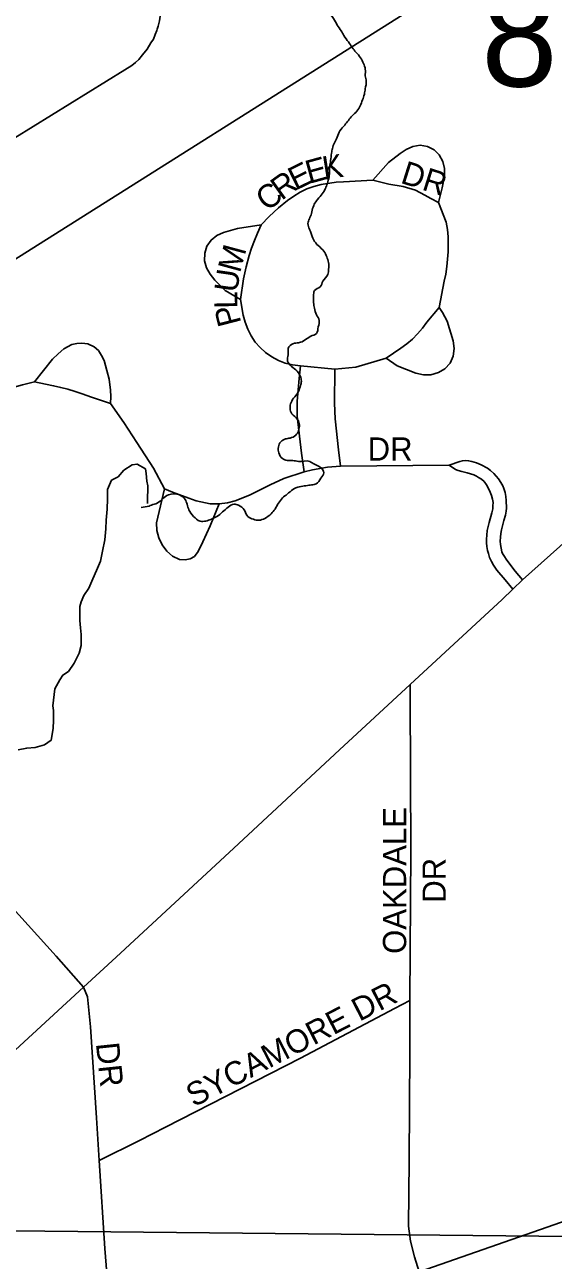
# Model space of a CAD drawing. Extents: x 1587405 to 1714697, y 1028970 to 1155083.
# Drawn here: x 1657853 to 1658990, y 1113359 to 1116017 of the extents above; entities that cross this region are included whole.
import ezdxf

# ---------------------------------------------------------------- set-up
doc = ezdxf.new("R2010")
doc.units = 0
for name, color, linetype in [('GM_X_City_Street', 7, 'Continuous'), ('GM_X_City_Street_Text', 7, 'Continuous'), ('GM_X_Minor_River', 7, 'Continuous'), ('GM_X_Rail_Line', 7, 'Continuous'), ('GM_X_Section', 7, 'Continuous'), ('GM_X_Section_Text', 7, 'Continuous'), ('GM_X_State_Route', 7, 'Continuous'), ('GM_X_US_Route', 7, 'Continuous')]:
    doc.layers.add(name, color=color, linetype=linetype)

msp = doc.modelspace()

# ---------------------------------------------------------------- linework, layer by layer
at = {"layer": 'GM_X_City_Street'}
for points in [[(1657832.1, 1115773.7), (1658068.7, 1115919.8), (1658083.3, 1115929.3), (1658091.2, 1115935.4), (1658098.7, 1115942.3), (1658106.7, 1115951.9), (1658116.3, 1115964.6), (1658124.7, 1115977.9), (1658129.8, 1115986.1), (1658134, 1115995.8), (1658137.4, 1116004.3), (1658138.2, 1116007.2), (1658140, 1116013.6), (1658142.8, 1116025.2), (1658145.6, 1116044.7)], [(1658743.2, 1115634.5), (1658751.3, 1115665.9), (1658756.1, 1115691.5), (1658755.8, 1115707.4), (1658752.2, 1115722.7), (1658744.7, 1115736.6), (1658733.6, 1115747.9), (1658719.5, 1115754.9), (1658703.9, 1115757.4), (1658688.3, 1115754.9), (1658673.8, 1115748.7), (1658660.7, 1115739.9), (1658635.6, 1115720.5), (1658601.9, 1115682.1)], [(1658601.9, 1115682.1), (1658539.2, 1115679.2), (1658522.9, 1115678.1), (1658490.7, 1115673.1), (1658475.2, 1115669.1), (1658460, 1115663.5), (1658445.5, 1115656.6), (1658431.7, 1115648.2), (1658418.7, 1115638.6), (1658399.2, 1115623.1), (1658378.9, 1115604.4), (1658361.8, 1115586.5)], [(1658743.2, 1115634.5), (1658726.9, 1115643.2), (1658713.8, 1115650), (1658693.4, 1115661), (1658666.9, 1115668.6), (1658636.5, 1115673.9), (1658601.9, 1115682.1)], [(1658744.9, 1115408.3), (1658755.4, 1115465), (1658758.9, 1115480.6), (1658761.4, 1115496.4), (1658763.8, 1115528.6), (1658763.8, 1115560.7), (1658762.3, 1115576.6), (1658759.5, 1115592.2), (1658743.2, 1115634.5)], [(1658361.8, 1115586.5), (1658310.7, 1115578.4), (1658280.7, 1115570.1), (1658266.3, 1115563.4), (1658254, 1115553.4), (1658245.1, 1115540.4), (1658240.4, 1115525.1), (1658240.1, 1115509.2), (1658244.2, 1115493.8), (1658251.9, 1115480), (1658262, 1115467.6), (1658284.6, 1115445.1), (1658317.4, 1115426)], [(1658361.8, 1115586.5), (1658353.7, 1115568.7), (1658347.1, 1115552.8), (1658341.2, 1115536.1), (1658336.2, 1115520.7), (1658329.4, 1115496.3), (1658323.6, 1115470.3), (1658317.4, 1115426)], [(1658317.4, 1115426), (1658323, 1115392.4), (1658327.2, 1115376.8), (1658332.9, 1115361.9), (1658340.3, 1115347.6), (1658349.1, 1115334.3), (1658359.5, 1115322.2), (1658371.4, 1115311.5), (1658384.5, 1115302.4), (1658398.8, 1115294.8), (1658413.3, 1115288.7), (1658428.8, 1115284.9), (1658446.5, 1115282.7)], [(1658630.8, 1115299.4), (1658662, 1115320.9), (1658674.9, 1115330.3), (1658687, 1115340.7), (1658698.3, 1115352), (1658708.7, 1115364.1), (1658718.2, 1115376.9), (1658744.9, 1115408.3)], [(1658630.8, 1115299.4), (1658654.1, 1115283.2), (1658694.5, 1115267.3), (1658710.6, 1115263.7), (1658727, 1115263.9), (1658742.9, 1115268.4), (1658757, 1115276.9), (1658768, 1115289.1), (1658774.9, 1115304.1), (1658776.9, 1115320.4), (1658774.9, 1115336.7), (1658761.7, 1115379), (1658751.7, 1115397.8), (1658744.9, 1115408.3)], [(1657874.1, 1115248.8), (1657912.9, 1115297.5), (1657924.9, 1115308.8), (1657937.6, 1115319.5), (1657954.3, 1115328.8), (1657965.5, 1115331.3), (1657976.1, 1115332.1), (1657988.9, 1115330.4), (1658002.8, 1115323.7), (1658011.5, 1115316), (1658018.6, 1115305.6), (1658023.8, 1115294.2), (1658029.9, 1115272.7), (1658034.9, 1115254.2), (1658037.6, 1115230.4), (1658038.7, 1115216.9), (1658037.6, 1115202.3)], [(1658454, 1115054.7), (1658448.5, 1115094.9), (1658439.4, 1115175.1), (1658438.9, 1115207.4), (1658443.7, 1115255.6), (1658446.5, 1115282.7)], [(1658446.5, 1115282.7), (1658520, 1115275.9)], [(1658520, 1115275.9), (1658565.1, 1115280.3), (1658630.8, 1115299.4)], [(1658532.4, 1115067.1), (1658528.4, 1115102.1), (1658520.6, 1115168.9), (1658519.2, 1115202.5), (1658520, 1115275.9)], [(1657693, 1114961.3), (1657695.7, 1114981.9), (1657694.6, 1115014.3), (1657691.3, 1115048.4), (1657690.2, 1115070.6), (1657692.4, 1115103.1), (1657699.7, 1115131.2), (1657708.8, 1115150.7), (1657719.2, 1115165.7), (1657728.3, 1115178), (1657738.1, 1115187.8), (1657748.7, 1115196.5), (1657760.4, 1115206.3), (1657773.8, 1115214.7), (1657788.1, 1115221.7), (1657803, 1115227.1), (1657822.7, 1115234.7), (1657848.2, 1115242.3), (1657874.1, 1115248.8)], [(1657874.1, 1115248.8), (1657898, 1115243.3), (1657915.3, 1115240.1), (1657930.5, 1115236.1), (1657946.2, 1115232.6), (1657961.6, 1115228.2), (1657976.6, 1115222.6), (1657997, 1115215.8), (1658037.6, 1115202.3)], [(1658037.6, 1115202.3), (1658066.6, 1115161.2), (1658094.3, 1115118), (1658130.1, 1115062.7), (1658153.5, 1115018.3)], [(1658454, 1115054.7), (1658472.2, 1115059.5), (1658504.1, 1115064.9), (1658532.4, 1115067.1)], [(1658532.4, 1115067.1), (1658765.9, 1115069.1)], [(1658765.9, 1115069.1), (1658789.2, 1115077.5), (1658794.7, 1115078.9), (1658801.2, 1115079.5), (1658807.8, 1115078.9), (1658814.8, 1115077.3), (1658825, 1115074.3), (1658835.1, 1115070), (1658848.3, 1115062.8), (1658855, 1115057.8), (1658862.3, 1115051.1), (1658872.3, 1115039.8), (1658877.2, 1115032.3), (1658881.5, 1115025.1), (1658883.8, 1115019.2), (1658886.3, 1115010.8), (1658887.9, 1115002), (1658888.6, 1114993.2), (1658889.2, 1114976.9), (1658888.8, 1114970.3), (1658887.2, 1114961.7), (1658883.8, 1114950.4), (1658880.9, 1114939.1), (1658878.4, 1114930.1), (1658877.3, 1114922.4), (1658876.7, 1114914.5), (1658876.1, 1114906.1), (1658876.7, 1114898.7), (1658877.8, 1114890.9), (1658879.6, 1114883.2), (1658881.1, 1114879.2), (1658883.4, 1114874.9), (1658889.9, 1114864.7), (1658908.1, 1114841), (1658924.1, 1114822.4)], [(1658765.9, 1115069.1), (1658779.8, 1115060.1), (1658785.6, 1115057.6), (1658793.3, 1115055.6), (1658804.9, 1115052.9), (1658811.9, 1115050.8), (1658818.9, 1115048.3), (1658825.2, 1115045.6), (1658829.5, 1115043.1), (1658835.6, 1115039.1), (1658841.5, 1115034.1), (1658846.5, 1115026.9), (1658849.9, 1115020.8), (1658854.2, 1115011.3), (1658857.3, 1115003.8), (1658859.1, 1114996.3), (1658860.5, 1114988.9), (1658860.3, 1114981.9), (1658859.8, 1114975.8), (1658857.8, 1114966.5), (1658852.1, 1114946.4), (1658848.1, 1114928.5), (1658846.9, 1114919), (1658846.3, 1114910.2), (1658846.6, 1114902.2), (1658847.4, 1114894.3), (1658848.8, 1114886), (1658850.4, 1114879.6), (1658852.9, 1114871), (1658857, 1114862.2), (1658861.5, 1114854), (1658869, 1114843.2), (1658886.3, 1114823), (1658903.1, 1114802.5)], [(1658271.3, 1114986.4), (1658289.3, 1114988.3), (1658305.8, 1114992.4), (1658336.8, 1115004.9), (1658381, 1115027), (1658410.4, 1115040.7), (1658454, 1115054.7)], [(1658153.5, 1115018.3), (1658136.6, 1114945.1), (1658137.3, 1114928.6), (1658141.8, 1114912.8), (1658148.9, 1114897.9), (1658158.8, 1114884.6), (1658171.2, 1114873.8), (1658186, 1114866.6), (1658198.3, 1114865.9), (1658208.9, 1114867.7), (1658218.4, 1114873.2), (1658226.5, 1114883.8), (1658236.5, 1114904.7), (1658251.7, 1114939), (1658271.3, 1114986.4)], [(1658153.5, 1115018.3), (1658170.9, 1115011.3), (1658206.2, 1114998.3), (1658222.1, 1114992.8), (1658252.1, 1114986.5), (1658271.3, 1114986.4)], [(1658681.8, 1113917.9), (1658683.6, 1114238.3), (1658682.6, 1114572.1), (1658682.5, 1114597.8)], [(1657979.6, 1113946.4), (1657921, 1114013.3), (1657799.6, 1114146.5), (1657706.1, 1114247.3)], [(1658013.5, 1113573.9), (1658007.7, 1113665.5), (1657994.4, 1113861.5), (1657988.3, 1113926), (1657979.6, 1113946.4)], [(1658013.5, 1113573.9), (1658100.1, 1113616.7), (1658156, 1113645.4), (1658446.3, 1113793.7), (1658648.9, 1113900.6), (1658681.8, 1113917.9)], [(1658701.9, 1113334), (1658691.9, 1113366.5), (1658682.8, 1113400.4), (1658679, 1113432.5), (1658679.8, 1113573.5), (1658681.2, 1113808.4), (1658681.8, 1113917.9)], [(1658047.6, 1113099.8), (1658045.8, 1113132.6), (1658025.5, 1113384.2), (1658013.5, 1113573.9)]]:
    msp.add_lwpolyline(points, dxfattribs=at)
at = {"layer": 'GM_X_Minor_River'}
msp.add_line((1658103.9, 1114978), (1658120.9, 1114981), dxfattribs=at)
msp.add_lwpolyline([(1658117, 1114987.1), (1658117.3, 1115001.1), (1658117.6, 1115015.2), (1658117.8, 1115025.2), (1658116, 1115035.2), (1658114.4, 1115051.3), (1658112.6, 1115061.4), (1658094.7, 1115071.8), (1658084.6, 1115070), (1658066.3, 1115058.3), (1658054, 1115044.5), (1658039.8, 1115036.8), (1658031.4, 1115016.9), (1658031, 1114996.8), (1658030.5, 1114974.8), (1658028, 1114950.8), (1658027.6, 1114932.7), (1658025.1, 1114908.7), (1658020.6, 1114884.7), (1658016.2, 1114862.8), (1658007.7, 1114842.9), (1657999.3, 1114825), (1657990.9, 1114805.1), (1657980.5, 1114789.3), (1657974.2, 1114775.3), (1657972, 1114765.4), (1657971.7, 1114749.3), (1657971.4, 1114735.3), (1657973.1, 1114719.2), (1657974.8, 1114705.1), (1657974.6, 1114693.1), (1657974.3, 1114681.1), (1657970, 1114665.1), (1657959.5, 1114643.3), (1657947.1, 1114625.5), (1657934.9, 1114617.7), (1657928.7, 1114607.8), (1657918.2, 1114587.9), (1657913.5, 1114551.9), (1657915.3, 1114541.9), (1657915.1, 1114531.8), (1657914.8, 1114519.8), (1657914.5, 1114503.8), (1657912.2, 1114489.8), (1657909.9, 1114477.8), (1657895.7, 1114468.1), (1657875.5, 1114462.4), (1657857.4, 1114460.8), (1657839.3, 1114457.1)], dxfattribs=at)
for points in [[(1658142.5, 1116670.5), (1658153.6, 1116657.7), (1658167.7, 1116653.7), (1658191.8, 1116649.6), (1658205.9, 1116647.6), (1658216, 1116649.6), (1658230.1, 1116643.5), (1658242.2, 1116635.5), (1658262.3, 1116627.4), (1658272.3, 1116619.3), (1658286.4, 1116607.2), (1658294.5, 1116595.2), (1658306.5, 1116583.1), (1658314.6, 1116573), (1658326.7, 1116558.9), (1658338.7, 1116546.9), (1658348.8, 1116540.8), (1658358.9, 1116538.8), (1658370.9, 1116534.7), (1658383, 1116532.7), (1658395.1, 1116524.6), (1658407.2, 1116518.6), (1658421.2, 1116510.5), (1658427.3, 1116500.5), (1658435.3, 1116488.4), (1658441.3, 1116476.3), (1658447.4, 1116462.2), (1658447.4, 1116450.2), (1658451.4, 1116438.1), (1658453.4, 1116426.1), (1658449.3, 1116401.9), (1658445.3, 1116389.9), (1658443.3, 1116375.8), (1658437.2, 1116365.8), (1658433.2, 1116351.7), (1658431.2, 1116341.7), (1658429.1, 1116329.6), (1658429.1, 1116317.6), (1658427.1, 1116305.5), (1658431.1, 1116281.4), (1658435.1, 1116269.3), (1658441.1, 1116257.2), (1658445.1, 1116243.2), (1658455.2, 1116227.1), (1658461.2, 1116217), (1658469.3, 1116202.9), (1658471.3, 1116190.9), (1658475.3, 1116180.8), (1658473.3, 1116170.8), (1658469.2, 1116146.6), (1658473.2, 1116118.5), (1658477.2, 1116102.4), (1658487.3, 1116084.3), (1658493.3, 1116074.2), (1658495.3, 1116062.2), (1658505.4, 1116046.1), (1658517.4, 1116030), (1658525.5, 1116015.9), (1658533.5, 1116003.8), (1658539.5, 1115993.8), (1658549.6, 1115979.7), (1658557.6, 1115967.6), (1658565.7, 1115957.6), (1658575.7, 1115945.5), (1658581.8, 1115933.4), (1658585.8, 1115921.3), (1658585.8, 1115907.2), (1658587.8, 1115895.2), (1658585.7, 1115879.1), (1658583.7, 1115867.1), (1658579.7, 1115855), (1658567.6, 1115830.9), (1658557.5, 1115820.9), (1658541.4, 1115800.8), (1658531.3, 1115788.8), (1658525.2, 1115774.7), (1658519.2, 1115762.7), (1658515.1, 1115750.6), (1658513.1, 1115740.6), (1658511.1, 1115724.5), (1658509.1, 1115712.4), (1658509, 1115698.4), (1658507, 1115686.3), (1658503, 1115672.2), (1658498.9, 1115662.2), (1658490.9, 1115650.1), (1658480.8, 1115638.1), (1658474.8, 1115628.1), (1658470.7, 1115614), (1658466.7, 1115601.9), (1658462.6, 1115591.9), (1658464.6, 1115579.8), (1658468.7, 1115569.8), (1658474.7, 1115553.7), (1658484.7, 1115541.6), (1658496.8, 1115529.5), (1658502.8, 1115517.5)], [(1658502.8, 1115517.5), (1658506.8, 1115505.4), (1658506.8, 1115491.3), (1658504.8, 1115479.3), (1658494.7, 1115465.2), (1658488.7, 1115453.2), (1658476.6, 1115445.1), (1658474.6, 1115433.1), (1658474.6, 1115419), (1658476.5, 1115407), (1658480.6, 1115392.9), (1658486.6, 1115380.8), (1658484.6, 1115366.8), (1658480.5, 1115352.7), (1658468.4, 1115346.7), (1658456.4, 1115338.7), (1658442.3, 1115332.7), (1658430.2, 1115330.7), (1658420.1, 1115320.6), (1658420.1, 1115310.6), (1658418.1, 1115296.5), (1658424.1, 1115284.4), (1658436.2, 1115274.4), (1658446.2, 1115260.3), (1658448.2, 1115250.2), (1658446.2, 1115240.2), (1658442.2, 1115228.1), (1658426, 1115204), (1658424, 1115192), (1658428, 1115179.9), (1658440.1, 1115167.8), (1658444.1, 1115155.8), (1658442.1, 1115143.7), (1658436, 1115133.7), (1658423.9, 1115127.7), (1658413.9, 1115125.7), (1658403.8, 1115119.7), (1658399.7, 1115095.6), (1658407.8, 1115083.5), (1658417.8, 1115079.4), (1658429.9, 1115079.4), (1658442, 1115077.4), (1658466.2, 1115077.3), (1658476.2, 1115071.3), (1658488.3, 1115065.2), (1658496.4, 1115053.2), (1658490.3, 1115041.1), (1658480.2, 1115029.1), (1658470.2, 1115027.1), (1658458.1, 1115025.1), (1658444, 1115023.1), (1658429.9, 1115017.1), (1658417.8, 1115007.1), (1658407.7, 1114999.1), (1658391.6, 1114975), (1658383.5, 1114964.9), (1658369.4, 1114954.9), (1658357.3, 1114950.9), (1658345.2, 1114952.9), (1658333.2, 1114959), (1658325.1, 1114973.1), (1658313.1, 1114983.1), (1658303, 1114985.2), (1658290.9, 1114979.2), (1658266.7, 1114959.1), (1658254.6, 1114953.1), (1658242.6, 1114949.1), (1658230.5, 1114949.1), (1658216.4, 1114959.2), (1658206.3, 1114973.3), (1658202.3, 1114985.3), (1658198.3, 1114995.4), (1658186.2, 1115005.5), (1658162.1, 1115005.5), (1658150, 1114997.5), (1658137.9, 1114987.5), (1658125.8, 1114983.5), (1658120.9, 1114981)]]:
    msp.add_spline(points, degree=3, dxfattribs=at)
at = {"layer": 'GM_X_Rail_Line'}
msp.add_lwpolyline([(1653567.6, 1112818.9), (1655299.9, 1113913.2), (1659869.5, 1116798.4), (1669730.9, 1123016.6), (1672358.5, 1124671.2), (1681694.7, 1130554.4), (1684436.5, 1132280.4), (1688526.9, 1134851.5), (1688806.9, 1135025.4), (1688953.3, 1135112.6), (1689086.8, 1135186.1), (1689267.7, 1135279.2), (1689470.2, 1135380.7), (1689588.1, 1135442), (1689734, 1135521.9), (1689883.6, 1135607.5), (1690363.1, 1135904.6), (1690749.1, 1136147.9), (1691069.9, 1136367.6)], dxfattribs=at)
at = {"layer": 'GM_X_Section'}
for points in [[(1656263, 1118717.5), (1661639.2, 1118644.5), (1661579.6, 1113384), (1656195.7, 1113439)], [(1661579.6, 1113384), (1661543.6, 1108095.1), (1656163.1, 1108222.1), (1656195.7, 1113439)]]:
    msp.add_lwpolyline(points, close=True, dxfattribs=at)
at = {"layer": 'GM_X_State_Route'}
msp.add_lwpolyline([(1656575, 1112579.7), (1656620.2, 1112627.5), (1656664.8, 1112676.4), (1656911.6, 1112922.1), (1657015, 1113027.6), (1657329.2, 1113340.2), (1657506.5, 1113511.2), (1657662.8, 1113655.9), (1657795.9, 1113778), (1657979.6, 1113946.4), (1658050.1, 1114011), (1658302.9, 1114245.4), (1658530.1, 1114457.2), (1658682.5, 1114597.8), (1658880.3, 1114780.2), (1658903.1, 1114802.5), (1658924.1, 1114822.4), (1659004, 1114894.2), (1659423.8, 1115281.1), (1659691.8, 1115528.9), (1659882, 1115704.8), (1660099.2, 1115905.5), (1660146.8, 1115947.6), (1660250.7, 1116036.2)], dxfattribs=at)
at = {"layer": 'GM_X_US_Route'}
msp.add_lwpolyline([(1656575, 1112579.7), (1656787, 1112653.2), (1656848.6, 1112676.2), (1657189, 1112795.7), (1658047.6, 1113099.8), (1658156.4, 1113138.9), (1658364.3, 1113212.3), (1658585.4, 1113289.9), (1658701.9, 1113334), (1659052.8, 1113456.4), (1659202.2, 1113509.2), (1659541.7, 1113629.4), (1659817.4, 1113726.9), (1660009.1, 1113794.7), (1660107.3, 1113829.5), (1660209.1, 1113859.4), (1660329.8, 1113892.8), (1660431.4, 1113914.5), (1660512.1, 1113930.2), (1660563.4, 1113938.9)], dxfattribs=at)

# ---------------------------------------------------------------- texts
at = {"layer": 'GM_X_City_Street_Text'}
for s, rotation, p in [('E', 15.3486, (1658464.9, 1115674.3)), ('K', 8.8226, (1658497.3, 1115683.3)), ('E', 26.2106, (1658435.6, 1115659.6)), ('DR', 342.4618, (1658659.4, 1115677.1)), ('R', 35.8792, (1658405.5, 1115637.6)), ('C', 36.729, (1658373.9, 1115614)), ('M', 74.8551, (1658316.1, 1115481.3)), ('U', 81.7308, (1658310.1, 1115439.3)), ('L', 91.1201, (1658310.9, 1115406.3)), ('P', 104.5002, (1658319.3, 1115375.3)), ('DR', 0, (1658590.8, 1115079.1)), ('OAKDALE', 90, (1658673.7, 1114018.1)), ('DR', 90, (1658758.8, 1114128.1)), ('SYCAMORE DR', 27.331, (1658216.8, 1113687.6)), ('DR', 276.0066, (1658006.1, 1113825.4))]:
    msp.add_text(s, height=50, rotation=rotation, dxfattribs=at).set_placement(p)
at = {"layer": 'GM_X_Section_Text'}
msp.add_text('8', height=221, rotation=0, dxfattribs=at).set_placement((1658835, 1115884))

doc.saveas('drawing.dxf')
